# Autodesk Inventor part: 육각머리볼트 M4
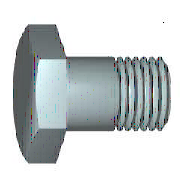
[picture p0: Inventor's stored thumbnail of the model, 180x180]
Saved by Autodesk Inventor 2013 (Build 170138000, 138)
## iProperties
IsCustomPart: 1
Created: 2012-02
Part Number: 육각머리볼트 M4
Material: 강철, 연강
Description: 6각 머리 볼트 및 6각 머리 나사
Document SubType Name: Modeling
Standard: KS B 1002
Designer: mduedu
Standards Organization: KS
Language: ko-KR
Size Designation: A + B M4 x 16
Categories: <MemberInstance><Categories><Category DisplayName="조임쇠" InternalName="e4da775c-781d-43d5-af7c-5136215cf5a6" Mnemonic="FSTN"><Category DisplayName="볼트" InternalN
Density: 7.86 g/cm^3
Mass: 2.45486 g
Surface Area: 3.4613 cm^2
Volume: 0.312323 cm^3
Author: mduedu
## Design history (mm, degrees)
sketch "스케치1"
  geometry: L1 (0, 2.94)-(0, 2); L2 (2.1, 2)-(16, 2); L3 (16, 2)-(16, 0); L4 (16, 0)-(-0.4, 0); L5 (-3.68, 0)-(19.28, 0) reference; L6 (-0.4, 0)-(-0.4, 2.94); L7 (-0.4, 2.94)-(0, 2.94); L8 (2.1, 2)-(1.67, 2); L9 (1.67, 2)-(0, 2); L10 (0, -0.588)-(0, 3.528) reference
  constraints: 16 end point, 2 collinear, 2 perpendicular, 1 parallel
  dimensions: "d0" = 16 distance between parallel lines of L3 L1 (= NLG); "d1" = 13.9 distance from line of L2.start L3 (= GEL); "d2" = 4 diameter of L2 L4 (= GD); "d9" = 0.4001 distance between parallel lines of L6 L1 (computed from SD); "d10" = 5.88 diameter of L7 L4 (= SD2); "d13" = 0.42952 distance of L2.start L8.end (computed from GAL); "d14" = 4 diameter of L9 L4 (= BDM)
revolve "본체" sketch "스케치1" stored, may be unused: angle "d12" = 90 deg
sketch "스케치2"
  geometry: L1 (0, 4.041)-(3.5, 2.021); L2 (3.5, 2.021)-(3.5, -2.021); L3 (3.5, -2.021)-(0, -4.041); L4 (0, -4.041)-(-3.5, -2.021); L5 (-3.5, -2.021)-(-3.5, 2.021); L6 (-3.5, 2.021)-(0, 4.041); 2 further points
  constraints: 12 end point, 1 coincident, 1 vertical, 11 other
  dimensions: "d11" = 7 distance between parallel lines of L5 L2 (= SW)
extrude "머리" join sketch "스케치2" distance "d3" = 2.4 (= KOH - SD); taper "d4" = 0 deg
sketch "스케치4"
  geometry: L1 (-2.8, 3.5)-(-2.8, 4.041); L2 (-2.8, 4.041)-(-2.487, 4.041); L3 (-2.487, 4.041)-(-2.8, 3.5); L4 (-3.28, 0)-(0.08, 0) reference; L5 (-0.4, 4.041)-(-2.8, 4.041) reference; L6 (-2.8, 2.021)-(-2.8, 4.041) reference
  constraints: 6 end point, 2 collinear, 1 perpendicular, 1 vertical
  dimensions: "d5" = 30 deg angle of L3 L1 (= ANG1); "d19" = 7 diameter of L1.start L4 (= SW0)
revolve "모따기1" sketch "스케치4" stored, may be unused: angle "d21" = 90 deg
workplane "Work Plane1"
body "Solid1"
feature "스레드" dims "d15" = 13.9 (= GEL), "d16" = 0
chamfer "모따기2" distance "d6" = 0.42941 (= -0.5 x SPD + 0.5 x GD); stored, may be unused: second distance "d7" = 0.42952 (computed from GUL), angle "d55" = 45 deg
other parameters: "NLG" = 16 [user parameter; used in 1 equation term], "GD" = 4 (= NND) [user parameter; used in 2 equation terms], "BDM" = 4 (= NND) [user parameter; used in 1 equation term], "KOH" = 2.8 [user parameter; used in 1 equation term], "GEL" = 13.9 [user parameter; used in 2 equation terms], "SW" = 7 [user parameter; used in 3 equation terms], "SW0" = 7 (= SW) [user parameter; used in 1 equation term], "SPD" = 3.14117 (= NND - 1.2269 x PTC) [user parameter; used in 1 equation term], "SD2" = 5.88 (= SDH) [user parameter; used in 1 equation term], "SD" = 0.4 [user parameter; used in 2 equation terms], "ANG1" = 30 deg [user parameter; used in 1 equation term], "GAL" = 0.42941 (= 0.61345 x PTC) [user parameter; used in 1 equation term], "GUL" = 0.42941 (= 0.61345 x PTC) [user parameter; used in 1 equation term], "d8" = 0, "RR" = 0.2 [user parameter], "d57" = 0, "d58" = 0, "TPU" = 14.28571 (computed from PTC) [user parameter], "GD1" = 3.14117 (= THREADDIA - 1.2269 x PTC) [user parameter], "THREADDIA" = 4 [user parameter; used in 1 equation term], "SDH" = 5.88 [user parameter; used in 1 equation term], "SDHG" = 2.1 [user parameter], "TOA" = 30 deg [user parameter], "PTC" = 0.7 [user parameter; used in 5 equation terms], "NND" = 4 [user parameter; used in 3 equation terms], "E0" = 8.085 (= 1.155 x SW) [user parameter]
